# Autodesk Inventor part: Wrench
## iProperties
Created: 2005-01
Part Number: Wrench
Document SubType Name: Modeling
Designer: Dale Schneider
Manufacturer: Standard
Standards Organization: Custom
Density: 1 g/cm^3
Author: Dale Schneider
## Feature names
1. Extrusion1
2. Hole1
3. Fillet1
